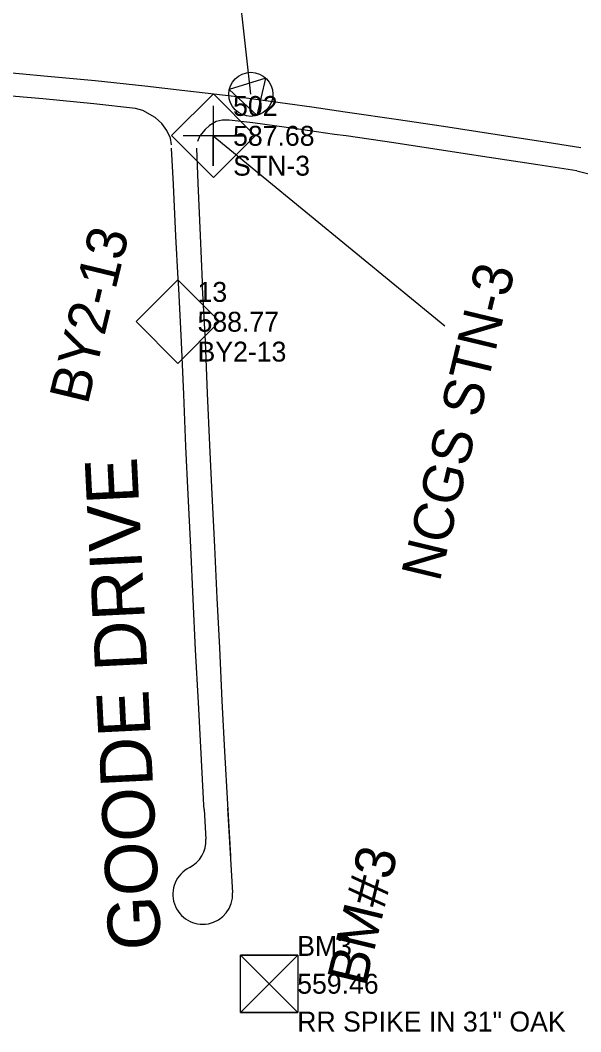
# Model space of a CAD drawing. Extents: x 1649669 to 1659218, y 588594 to 607900.
# Drawn here: x 1653992 to 1654554, y 600375 to 601392 of the extents above; entities that cross this region are included whole.
import ezdxf

# ---------------------------------------------------------------- set-up
doc = ezdxf.new("R2010")
doc.units = 0
for name, color, linetype in [('CTL Bench Mark CELL', 7, 'Continuous'), ('CTL Bench Mark Cogo Comment', 7, 'Continuous'), ('CTL Bench Mark Cogo Elevation', 7, 'Continuous'), ('CTL Bench Mark Cogo Number', 7, 'Continuous'), ('CTL Bench Mark Text', 7, 'Continuous'), ('CTL NCGS Vertical CELL', 7, 'Continuous'), ('CTL NCGS Vertical Cogo Comment', 7, 'Continuous'), ('CTL NCGS Vertical Cogo Elevation', 7, 'Continuous'), ('CTL NCGS Vertical Cogo Number', 7, 'Continuous'), ('CTL NCGS Vertical Leader', 7, 'Continuous'), ('CTL NCGS Vertical Text', 7, 'Continuous'), ('CTL NGS Horizontal CELL', 7, 'Continuous'), ('CTL NGS Horizontal Leader', 7, 'Continuous'), ('CTL Supplemental Horizontal and Vertical CELL', 7, 'Continuous'), ('CTL Supplemental Horizontal and Vertical Cogo Comment', 7, 'Continuous'), ('CTL Supplemental Horizontal and Vertical Cogo Elevation', 7, 'Continuous'), ('CTL Supplemental Horizontal and Vertical Cogo Number', 7, 'Continuous'), ('CTL Supplemental Horizontal and Vertical Text', 7, 'Continuous'), ('Exist Roads EOP', 7, 'Continuous'), ('Sheet Data Field CELL', 7, 'Continuous')]:
    doc.layers.add(name, color=color, linetype=linetype)

# ---------------------------------------------------------------- blocks, each defined once
blk = doc.blocks.new('CTL NGS HORIZONTAL')
at = {"layer": 'CTL NGS Horizontal CELL'}
blk.add_line((0, 0), (0, 0), dxfattribs=at)
blk.add_lwpolyline([(-0.0638, -0.0372), (0.0638, -0.0372), (0, 0.0737), (-0.0638, -0.0372)], dxfattribs=at)
blk.add_circle((0, 0), 0.0738, dxfattribs=at)

msp = doc.modelspace()

# ---------------------------------------------------------------- linework, layer by layer
at = {"layer": 'CTL Bench Mark CELL'}
msp.add_line((1654241.7, 600423.6), (1654241.7, 600423.6), dxfattribs=at)
msp.add_lwpolyline([(1654212.9, 600452.3), (1654270.4, 600452.3), (1654270.4, 600394.8), (1654212.9, 600394.8)], close=True, dxfattribs=at)
for points in [[(1654270.4, 600452.3), (1654212.9, 600394.8), (1654241.7, 600423.6), (1654270.4, 600394.8), (1654212.9, 600452.3)], [(1654241.7, 600423.6), (1654270.4, 600452.3), (1654212.9, 600452.3), (1654241.7, 600423.6)], [(1654241.7, 600423.6), (1654212.9, 600394.8), (1654270.4, 600394.8), (1654241.7, 600423.6)]]:
    msp.add_lwpolyline(points, dxfattribs=at)
at = {"layer": 'CTL NCGS Vertical CELL'}
msp.add_line((1654185.3, 601275.5), (1654185.3, 601275.5), dxfattribs=at)
msp.add_lwpolyline([(1654185.3, 601305.5), (1654185.3, 601245.5), (1654185.3, 601275.5), (1654215.3, 601275.5), (1654155.3, 601275.5)], dxfattribs=at)
at = {"layer": 'CTL NCGS Vertical Leader'}
msp.add_lwpolyline([(1654185.3, 601275.5), (1654417.9, 601084.7)], dxfattribs=at)
at = {"layer": 'CTL NGS Horizontal Leader'}
msp.add_lwpolyline([(1654223.1, 601317.2), (1654187.6, 601636.4), (1654198.1, 601679.9)], dxfattribs=at)
at = {"layer": 'CTL Supplemental Horizontal and Vertical CELL'}
for p, q in [((1654185.3, 601275.5), (1654185.3, 601275.5)), ((1654149.6, 601088.7), (1654149.6, 601088.7))]:
    msp.add_line(p, q, dxfattribs=at)
for points in [[(1654143.6, 601275.7), (1654185.5, 601317.6), (1654227.5, 601275.6), (1654185.6, 601233.7)], [(1654107.9, 601088.8), (1654149.8, 601130.8), (1654191.8, 601088.8), (1654149.9, 601046.8)]]:
    msp.add_lwpolyline(points, close=True, dxfattribs=at)
at = {"layer": 'Exist Roads EOP'}
for p, q in [((1654145.4, 601226.6), (1654143.4, 601263.1)), ((1654168.4, 601263.2), (1654169.8, 601227.9)), ((1654550.5, 601240.4), (1654599.2, 601228.1)), ((1654147.8, 601174.8), (1654145.4, 601226.6)), ((1654169.8, 601227.9), (1654172.2, 601175.4)), ((1654150.2, 601131.8), (1654147.8, 601174.8)), ((1654172.2, 601175.4), (1654174.1, 601128.6)), ((1654150.7, 601122.2), (1654150.2, 601131.8)), ((1654174.1, 601128.6), (1654174.3, 601123.4)), ((1654153.5, 601068.3), (1654150.7, 601122.2)), ((1654174.3, 601123.4), (1654177.1, 601069)), ((1654155.7, 601015.5), (1654153.5, 601068.3)), ((1654177.1, 601069), (1654179.3, 601016.9)), ((1654157.9, 600963.5), (1654155.7, 601015.5)), ((1654179.3, 601016.9), (1654181.5, 600964.8)), ((1654160.2, 600915), (1654157.9, 600963.5)), ((1654181.5, 600964.8), (1654184, 600915.5)), ((1654162.7, 600862.4), (1654160.2, 600915)), ((1654184, 600915.5), (1654186.5, 600862.6)), ((1654165.3, 600810.1), (1654162.7, 600862.4)), ((1654186.5, 600862.6), (1654189.1, 600811.1)), ((1654167.7, 600759.2), (1654165.3, 600810.1)), ((1654189.1, 600811.1), (1654191.5, 600761)), ((1654170.5, 600706.2), (1654167.7, 600759.2)), ((1654191.5, 600761), (1654194.1, 600707.7)), ((1654173.2, 600654.9), (1654170.5, 600706.2)), ((1654194.1, 600707.7), (1654196.8, 600657)), ((1654196.8, 600657), (1654199.6, 600603.9)), ((1654176.1, 600598.8), (1654178, 600568.8)), ((1654199.6, 600603.9), (1654202.7, 600552)), ((1654199.8, 600600.1), (1654204.7, 600515.1))]:
    msp.add_line(p, q, dxfattribs=at)
for points in [[(1653961.6, 601340.9), (1654019, 601335.5), (1654066.8, 601331), (1654116.7, 601325.7), (1654156.8, 601321), (1654206.4, 601315.2), (1654235.6, 601311.2), (1654284.3, 601304.6), (1654317.9, 601299.5), (1654322.7, 601299)], [(1654143.3, 601266.5), (1654142.3, 601273.1), (1654138.6, 601280.8), (1654133.7, 601288), (1654126.9, 601294), (1654114.8, 601301), (1654107.3, 601302.9), (1654065.5, 601307.5), (1654014.2, 601312.6), (1653958.8, 601317.5)], [(1654322.7, 601299), (1654369.2, 601292.1), (1654416.6, 601285.2), (1654466.3, 601277.5), (1654514.3, 601270.1), (1654554.5, 601263.8)], [(1654318.8, 601275.4), (1654307.1, 601277), (1654271.1, 601282.2), (1654225, 601288.5), (1654201.2, 601291.4), (1654194.3, 601291.2), (1654188.2, 601289.9), (1654181.7, 601286), (1654177.3, 601282), (1654171.9, 601275.5), (1654169.7, 601269.8)], [(1654550.5, 601240.4), (1654511.3, 601246.4), (1654462.4, 601253.8), (1654412.4, 601261.5), (1654366.8, 601268.4), (1654318.8, 601275.4)], [(1654176.1, 600598.8), (1654175.8, 600603.1), (1654173.2, 600654.9)]]:
    msp.add_lwpolyline(points, dxfattribs=at)
for centre, start, end in [((1654148.1, 600567.2), 296.436, 3.1459), ((1654174.8, 600513.4), 116.436, 3.0906)]:
    msp.add_arc(centre, 30, start, end, dxfattribs=at)

# ---------------------------------------------------------------- block references
at = {"layer": 'CTL NGS Horizontal CELL', "xscale": 300, "yscale": 300, "rotation": -42.96908576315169}
msp.add_blockref('CTL NGS HORIZONTAL', (1654223.1, 601317.2), dxfattribs=at)

# ---------------------------------------------------------------- texts
at = {"layer": 'CTL Bench Mark Cogo Comment'}
msp.add_text('RR SPIKE IN 31" OAK', height=20, dxfattribs=at).set_placement((1654269.7, 600375.6))
at = {"layer": 'CTL Bench Mark Cogo Elevation'}
msp.add_text('559.46', height=20, dxfattribs=at).set_placement((1654269.7, 600413.6))
at = {"layer": 'CTL Bench Mark Cogo Number'}
msp.add_text('BM3', height=20, dxfattribs=at).set_placement((1654269.7, 600451.6))
at = {"layer": 'CTL Bench Mark Text'}
msp.add_text('BM#3', height=40, rotation=76.4261, dxfattribs=at).set_placement((1654338.2, 600419.8))
at = {"layer": 'CTL NCGS Vertical Cogo Comment'}
msp.add_text('STN-3', height=20, dxfattribs=at).set_placement((1654205.3, 601235.5))
at = {"layer": 'CTL NCGS Vertical Cogo Elevation'}
msp.add_text('587.68', height=20, dxfattribs=at).set_placement((1654205.3, 601265.5))
at = {"layer": 'CTL NCGS Vertical Cogo Number'}
msp.add_text('502', height=20, dxfattribs=at).set_placement((1654205.3, 601295.5))
at = {"layer": 'CTL NCGS Vertical Text'}
msp.add_text('NCGS STN-3', height=40, rotation=76.4261, dxfattribs=at).set_placement((1654412.7, 600826.4))
at = {"layer": 'CTL Supplemental Horizontal and Vertical Cogo Comment'}
msp.add_text('BY2-13', height=20, dxfattribs=at).set_placement((1654169.6, 601048.7))
at = {"layer": 'CTL Supplemental Horizontal and Vertical Cogo Elevation'}
msp.add_text('588.77', height=20, dxfattribs=at).set_placement((1654169.6, 601078.7))
at = {"layer": 'CTL Supplemental Horizontal and Vertical Cogo Number'}
msp.add_text('13', height=20, dxfattribs=at).set_placement((1654169.6, 601108.7))
at = {"layer": 'CTL Supplemental Horizontal and Vertical Text'}
msp.add_text('BY2-13', height=40, rotation=76.4261, dxfattribs=at).set_placement((1654059.2, 601004.4))
at = {"layer": 'Sheet Data Field CELL'}
msp.add_text('GOODE DRIVE', height=52.501, rotation=92.835, dxfattribs=at).set_placement((1654133.1, 600458.6))

doc.saveas('drawing.dxf')
